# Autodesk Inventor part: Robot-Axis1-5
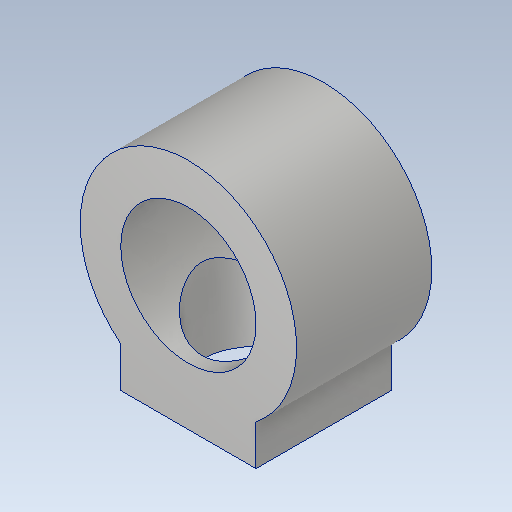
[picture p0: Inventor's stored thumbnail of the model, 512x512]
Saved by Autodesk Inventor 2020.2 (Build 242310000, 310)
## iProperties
Created: 2018-07
Part Number: Robot-Axis1-5
Material: Aluminum 6061
Description: 123456
Document SubType Name: Modeling
Designer: Power User
Mass: 394.75 g
Surface Area: 293.447 cm^2
Volume: 146.204 cm^3
Density: 2.7 g/cm^3
Appearance: Aluminum - Flat
Title: GEAR
Author: Power User
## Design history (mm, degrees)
sketch "Sketch6"
  geometry: L1 (-25, 16.58)-(25, 16.58); L2 (25, 16.58)-(25, 0); L3 (25, 0)-(-25, 0); L4 (-25, 0)-(-25, 16.58); C1 r 40 at (0, 46.2); C2 r 25 at (0, 46.2); 2 further points
  constraints: 8 end point, 2 centre point, 2 coincident, 2 parallel, 1 horizontal, 1 midpoint, 1 perpendicular
  dimensions: "d44" = 80 diameter of C1; "d45" = 46.2 distance of point (0, 0) C1.centre; "d46" = 50 distance of L2.end L3.end; "d47" = 50 diameter of C2
extrude "Extrusion5" new body sketch "Sketch6" stored distance "d48" = 50; taper "d49" = 0 deg
sketch "Sketch7"
  geometry: C1 r 20 at (25, -25); 1 further point
  constraints: 1 centre point, 1 coincident
  dimensions: "d50" = 40 diameter of C1
extrude "Extrusion6" cut sketch "Sketch7" stored distance "d51" = 50; taper "d52" = 0 deg
body "Solid2"
